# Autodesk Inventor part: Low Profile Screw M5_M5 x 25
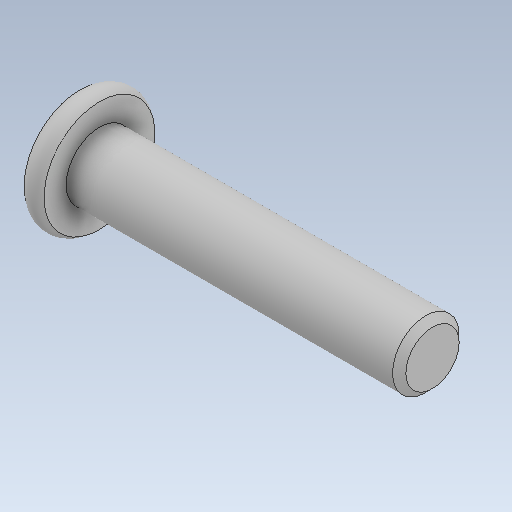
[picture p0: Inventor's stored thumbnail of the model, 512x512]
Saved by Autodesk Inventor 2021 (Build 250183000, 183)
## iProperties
Created: 2026-10
Part Number: Low Profile Screw M5_M5 x 25
Material: Steel
Document SubType Name: Modeling
Designer: hp
Density: 7.85 g/cm^3
Appearance: Default
Author: hp
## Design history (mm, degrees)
feature "Body1"
body "Solid1"
